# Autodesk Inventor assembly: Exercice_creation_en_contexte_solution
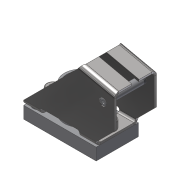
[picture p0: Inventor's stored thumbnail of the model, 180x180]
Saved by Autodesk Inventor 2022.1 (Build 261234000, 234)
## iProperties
Created: 2018-06
Part Number: Exercice_creation_en_contexte_solution
Material: Générique
Document SubType Name: Assembly
Designer: Fabian Perrée
Mass: 105.136 g
Surface Area: 173.547 cm^2
Volume: 19.7524 cm^3
Density: 5.32267 g/cm^3
Author: Fabian Perrée
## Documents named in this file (6)
- C:\Users\Fabian\Google Drive\01_Giup\01_Clients\07_ENI\Manuscrit\Fichiers_exercice\Chapitre_06\Exercice_creation_en_contexte\Exercice_creation_en_contexte_solution.iam
- C:\Users\Fabian\Google Drive\01_Giup\01_Clients\07_ENI\Manuscrit\Fichiers_exercice\Chapitre_06\Exercice_creation_en_contexte\Composants\Etrier_tole.ipt
- C:\Users\Fabian\Google Drive\01_Giup\01_Clients\07_ENI\Manuscrit\Fichiers_exercice\CC\ISO 4762 - M5 x 8ISO.ipt
- C:\Users\Fabian\Google Drive\01_Giup\01_Clients\07_ENI\Manuscrit\Fichiers_exercice\Chapitre_06\Exercice_creation_en_contexte\Composants\Chapeau_capteur.ipt
- C:\Users\Fabian\Google Drive\01_Giup\01_Clients\07_ENI\Manuscrit\Fichiers_exercice\Chapitre_06\Exercice_creation_en_contexte\Composants\Bille_18.ipt
- C:\Users\Fabian\Google Drive\01_Giup\01_Clients\07_ENI\Manuscrit\Fichiers_exercice\Axe.ipt
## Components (6 placed, 5 different names)
1. Etrier_tole:1 — Logement:3, Logement:4, Affleurement:1, Affleurement:2
2. Chapeau_capteur:1 — Logement:3, Logement:4
3. Bille_18:1
4. ISO 4762 M5 x 8:1
5. ISO 4762 M5 x 8:2
6. Axe:1 — Affleurement:1, Affleurement:2
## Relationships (4: Insert 2, Flush 2)
- Logement:3 [Insert]: Etrier_tole:1 ↔ Chapeau_capteur:1
- Logement:4 [Insert]: Etrier_tole:1 ↔ Chapeau_capteur:1
- Affleurement:1 [Flush]: Etrier_tole:1 ↔ Axe:1
- Affleurement:2 [Flush]: Etrier_tole:1 ↔ Axe:1
